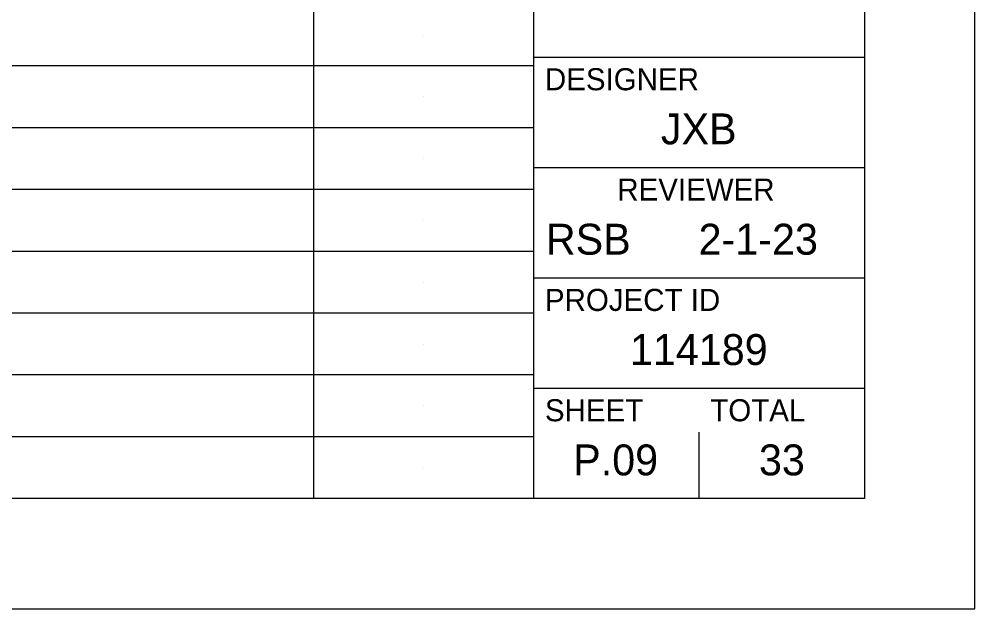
# Model space of a CAD drawing. Extents: x 0 to 34, y 0 to 22.
# Drawn here: x 29.665 to 34, y 0 to 2.672 of the extents above; entities that cross this region are included whole.
import ezdxf

# ---------------------------------------------------------------- set-up
doc = ezdxf.new("R2010")
doc.units = 0
for name, color, linetype in [('SC_Scratch1', 7, 'Continuous'), ('SH_Border', 7, 'Continuous'), ('SH_Cut_Line', 7, 'Continuous'), ('SH_Data', 7, 'Continuous')]:
    doc.layers.add(name, color=color, linetype=linetype)

msp = doc.modelspace()

# ---------------------------------------------------------------- linework, layer by layer
at = {"layer": 'SC_Scratch1'}
for p, q in [((31.5, 2.6), (31.5, 2.6)), ((31.5, 2.32), (31.5, 2.32)), ((31.5, 2.04), (31.5, 2.04)), ((31.5, 1.76), (31.5, 1.76)), ((31.5, 1.48), (31.5, 1.48)), ((31.5, 1.2), (31.5, 1.2)), ((31.5, 0.92), (31.5, 0.92)), ((31.5, 0.64), (31.5, 0.64))]:
    msp.add_line(p, q, dxfattribs=at)
at = {"layer": 'SH_Border'}
for p, q in [((32, 0.5), (32, 21.5)), ((32, 2.5), (33.5, 2.5)), ((32, 2), (33.5, 2)), ((32, 1.5), (33.5, 1.5)), ((32, 1), (33.5, 1))]:
    msp.add_line(p, q, dxfattribs=at)
msp.add_lwpolyline([(1.5, 21.5), (33.5, 21.5), (33.5, 0.5), (1.5, 0.5)], close=True, dxfattribs=at)
at = {"layer": 'SH_Cut_Line'}
msp.add_lwpolyline([(0, 0), (34, 0), (34, 22), (0, 22)], close=True, dxfattribs=at)
at = {"layer": 'SH_Data'}
for p, q in [((31, 21.5), (31, 0.5)), ((32, 2.46), (1.5, 2.46)), ((32, 2.18), (1.5, 2.18)), ((32, 1.9), (1.5, 1.9)), ((32, 1.62), (1.5, 1.62)), ((32, 1.34), (1.5, 1.34)), ((32, 1.06), (1.5, 1.06)), ((32.75, 0.5), (32.75, 0.8)), ((32, 0.78), (1.5, 0.78)), ((32.375, 0.675), (32.375, 0.675))]:
    msp.add_line(p, q, dxfattribs=at)

# ---------------------------------------------------------------- texts
for s, height, p in [('DESIGNER', 0.1, (32.05, 2.35)), ('JXB', 0.14, (32.5758, 2.105)), ('REVIEWER', 0.1, (32.3783, 1.85)), ('RSB', 0.14, (32.0541, 1.605)), ('2-1-23', 0.14, (32.7469, 1.605)), ('PROJECT ID', 0.1, (32.05, 1.35)), ('114189', 0.14, (32.4354, 1.105)), ('SHEET', 0.1, (32.05, 0.85)), ('TOTAL', 0.1, (32.8, 0.85)), ('P.09', 0.14, (32.1782, 0.605)), ('33', 0.14, (33.0207, 0.605))]:
    msp.add_text(s, height=height, dxfattribs=at).set_placement(p)

doc.saveas('drawing.dxf')
